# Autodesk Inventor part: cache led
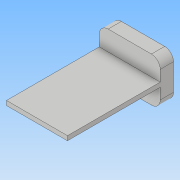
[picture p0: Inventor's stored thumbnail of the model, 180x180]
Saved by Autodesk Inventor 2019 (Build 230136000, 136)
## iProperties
Created: 2024-12
Part Number: cache led
Material: Générique
Document SubType Name: Modeling
Designer: admin
Density: 1 g/cm^3
Appearance: Par défaut
Author: admin
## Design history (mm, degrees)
sketch "Esquisse1"
  geometry: L1 (-6.734, 5.472)-(7.066, 5.472); L2 (7.066, 5.472)-(7.066, -4.528); L3 (7.066, -4.528)-(-6.734, -4.528); L4 (-6.734, -4.528)-(-6.734, 5.472); 1 further point
  constraints: 8 end point, 2 parallel, 1 horizontal, 1 perpendicular
  dimensions: "d0" = 13.8 distance of L1.start L1.end; "d1" = 10 distance of L1.end L2.end
extrude "Extrusion1" new body sketch "Esquisse1" distance "d2" = 3; taper "d3" = 0 deg
sketch "Esquisse2"
  geometry: L1 (-6.734, 5.472)-(-6.734, -4.528) reference; L2 (-6.734, 0.472)-(7.066, 0.472); L3 (7.066, -4.528)-(7.066, 5.472) reference; L4 (-6.734, 0.972)-(7.066, 0.972); L5 (7.066, 0.972)-(7.066, -0.028); L6 (7.066, -0.028)-(-6.734, -0.028); L7 (-6.734, -0.028)-(-6.734, 0.972); 1 further point
  constraints: 10 end point, 2 midpoint, 2 parallel, 2 point on line, 1 horizontal, 1 perpendicular
  dimensions: "d4" = 1 distance between parallel lines of L4 L6; "d5" = 0.5 distance between parallel lines of L4 L2
extrude "Extrusion2" join sketch "Esquisse2" distance "d6" = 21; taper "d7" = 0 deg
fillet "Congé1" dims "d8" = 2
node "Solide1"
